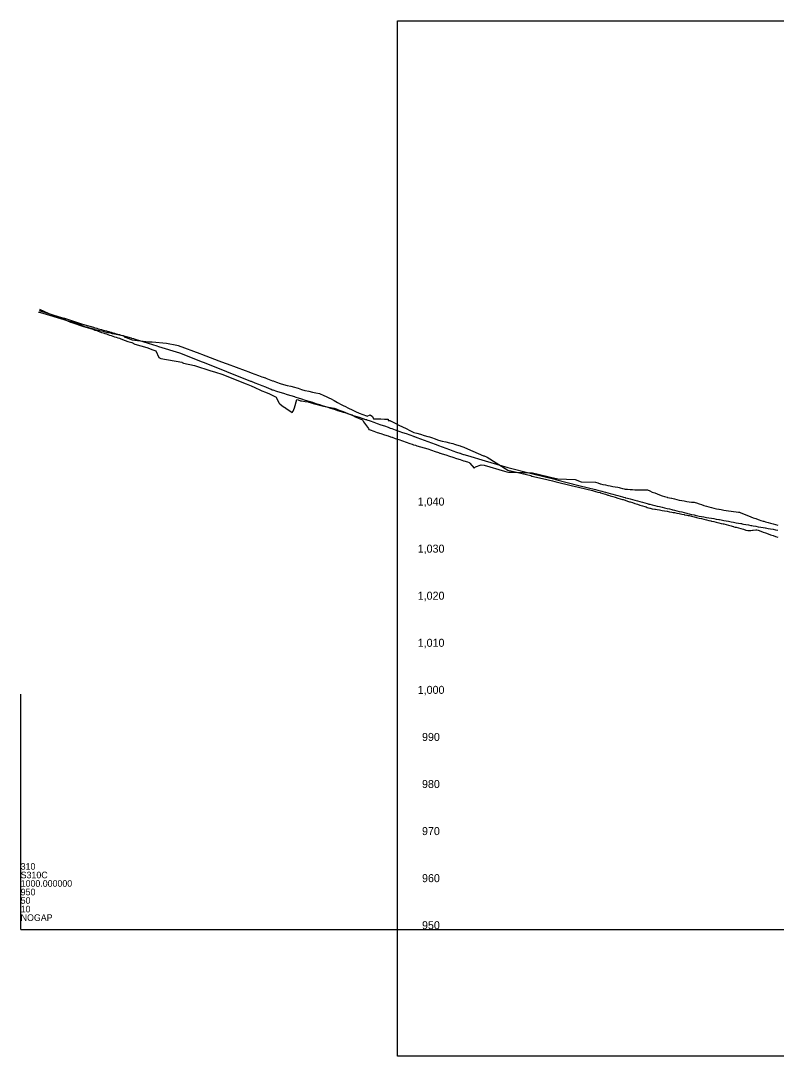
# Model space of a CAD drawing. Extents: x 1590191 to 1593577, y 1108634 to 1115609.
# Drawn here: x 1590279 to 1591081, y 1114509 to 1115609 of the extents above; entities that cross this region are included whole.
import ezdxf

# ---------------------------------------------------------------- set-up
doc = ezdxf.new("R2010")
doc.units = 0
for name, color, linetype in [('BR_EXIST_GROUND_LT', 7, 'Continuous'), ('BR_EXIST_GROUND_RT', 7, 'Continuous'), ('RD_DDB_ElevTX', 7, 'Continuous'), ('RD_DDB_Profile_EX', 7, 'Continuous'), ('RD_GPK_Profile_Cell', 7, 'Continuous'), ('RD_SHT_ShtClip', 7, 'Continuous')]:
    doc.layers.add(name, color=color, linetype=linetype)

msp = doc.modelspace()

# ---------------------------------------------------------------- linework, layer by layer
at = {"layer": 'BR_EXIST_GROUND_LT'}
msp.add_lwpolyline([(1590297.9, 1115299.3), (1590298.7, 1115299.2), (1590302.4, 1115298), (1590324.9, 1115291.5), (1590331.7, 1115289.4), (1590332.7, 1115289.1), (1590334.3, 1115288.6), (1590337, 1115287.9), (1590339.4, 1115287.2), (1590343.4, 1115285.5), (1590347.6, 1115283.6), (1590348.5, 1115283.4), (1590356.2, 1115281.3), (1590357.9, 1115280.8), (1590359.7, 1115280.4), (1590361.2, 1115280), (1590363.1, 1115279.6), (1590364.8, 1115279.2), (1590366.5, 1115278.8), (1590368.3, 1115278.4), (1590370, 1115278), (1590371.7, 1115277.6), (1590372.6, 1115277.4), (1590373.4, 1115277.4), (1590374.4, 1115277.3), (1590375.2, 1115277), (1590376.2, 1115276.6), (1590376.9, 1115276.5), (1590378.6, 1115276.1), (1590380.3, 1115275.7), (1590382, 1115275.4), (1590383.8, 1115275), (1590385.5, 1115274.6), (1590387.2, 1115274.3), (1590387.7, 1115274.2), (1590389.6, 1115272.6), (1590391, 1115272.1), (1590397.5, 1115269.8), (1590414.8, 1115267.6), (1590418.5, 1115267.8), (1590434, 1115266.3), (1590444.9, 1115264), (1590446.3, 1115263.8), (1590469.4, 1115255.1), (1590471.1, 1115254.5), (1590489.5, 1115247.5), (1590496.1, 1115244.8), (1590498.4, 1115244.2), (1590517.4, 1115237.3), (1590521.3, 1115235.6), (1590523.7, 1115234.7), (1590527.5, 1115233.3), (1590531.4, 1115232), (1590535.2, 1115230.6), (1590539, 1115229.3), (1590539.4, 1115229.1), (1590542.8, 1115227.7), (1590546.4, 1115226.3), (1590547, 1115226.1), (1590550.5, 1115224.8), (1590554.6, 1115223.3), (1590558.2, 1115222.3), (1590562, 1115221.3), (1590565.8, 1115220.4), (1590569.6, 1115219.4), (1590572.2, 1115218.8), (1590573.5, 1115218.4), (1590577.3, 1115217.1), (1590580.7, 1115216), (1590581.1, 1115215.9), (1590585, 1115215.1), (1590588.8, 1115214.2), (1590592.6, 1115213.4), (1590596.4, 1115212.7), (1590597.1, 1115212.5), (1590600.3, 1115211), (1590604.1, 1115209.2), (1590606.8, 1115207.9), (1590607.9, 1115207.3), (1590611.8, 1115205.3), (1590615.6, 1115203.2), (1590619.4, 1115201.2), (1590622.3, 1115199.7), (1590623.2, 1115199.2), (1590627.1, 1115197.3), (1590630.9, 1115195.4), (1590633, 1115194.3), (1590634.7, 1115193.6), (1590638.6, 1115192), (1590642.4, 1115190.5), (1590646.2, 1115188.9), (1590647, 1115188.6), (1590650.1, 1115190.2), (1590652.6, 1115188.2), (1590653.8, 1115185.9), (1590655.2, 1115185.9), (1590657.7, 1115185.8), (1590661.5, 1115185.7), (1590665.4, 1115185.6), (1590669.3, 1115185.4), (1590669.3, 1115183.9), (1590671.3, 1115183.9), (1590671.4, 1115183.8), (1590671.8, 1115183.7), (1590673, 1115183.1), (1590676.8, 1115181.1), (1590680.7, 1115179.2), (1590684.5, 1115177.3), (1590688.3, 1115175.4), (1590692.2, 1115173.6), (1590696.6, 1115171.5), (1590699.8, 1115170.5), (1590703.6, 1115169.4), (1590707.5, 1115168.3), (1590711.3, 1115167.2), (1590713.1, 1115166.7), (1590715.1, 1115165.9), (1590719, 1115164.5), (1590721.8, 1115163.5), (1590722.8, 1115163.2), (1590726.6, 1115162.2), (1590730.4, 1115161.3), (1590734.3, 1115160.4), (1590738.1, 1115159.5), (1590739.8, 1115159.1), (1590741.9, 1115158.4), (1590745.8, 1115157.2), (1590746.6, 1115156.9), (1590749.6, 1115155.6), (1590753.4, 1115154), (1590770.4, 1115146.7), (1590771.3, 1115146.6), (1590774.3, 1115145.1), (1590796.5, 1115131.2), (1590820.8, 1115125.5), (1590821.8, 1115125.1), (1590833.3, 1115122.5), (1590843.9, 1115119.9), (1590846.3, 1115119.3), (1590865, 1115114.8), (1590871.5, 1115113.1), (1590886.1, 1115109.6), (1590889.4, 1115108.7), (1590892, 1115108), (1590894.3, 1115107.5), (1590894.6, 1115107.4), (1590897.3, 1115106.5), (1590899.9, 1115105.7), (1590902.5, 1115104.9), (1590903.4, 1115104.6), (1590905.1, 1115104.1), (1590907.7, 1115103.3), (1590910.4, 1115102.5), (1590913, 1115101.7), (1590915.6, 1115100.9), (1590918.2, 1115100.2), (1590918.8, 1115100), (1590920.8, 1115099.3), (1590923.5, 1115098.5), (1590925.4, 1115097.8), (1590926.1, 1115097.6), (1590928.7, 1115096.8), (1590931.3, 1115096), (1590933.9, 1115095.1), (1590936.5, 1115094.3), (1590939.2, 1115093.5), (1590941.8, 1115092.6), (1590943.3, 1115092.2), (1590944.4, 1115091.8), (1590947, 1115090.9), (1590947.4, 1115090.8), (1590949.6, 1115090.4), (1590952.3, 1115090), (1590953.2, 1115089.8), (1590954.9, 1115089.5), (1590957.5, 1115089.1), (1590960.1, 1115088.6), (1590962.7, 1115088.1), (1590965.4, 1115087.6), (1590968, 1115087.1), (1590970.6, 1115086.7), (1590972, 1115086.4), (1590973.2, 1115086.2), (1590975.8, 1115085.7), (1590978.4, 1115085.2), (1590981.1, 1115084.6), (1590983.7, 1115084.1), (1590984.1, 1115084), (1590986.3, 1115083.6), (1590987.7, 1115083.3), (1590988.9, 1115083), (1590991.5, 1115082.4), (1590994.2, 1115081.7), (1590996.8, 1115081.1), (1590999.4, 1115080.5), (1591002, 1115079.9), (1591004.6, 1115079.2), (1591007.3, 1115078.6), (1591009.9, 1115078), (1591011.9, 1115077.5), (1591012.5, 1115077.3), (1591015.1, 1115076.7), (1591017.7, 1115076.1), (1591020.3, 1115075.4), (1591023, 1115074.8), (1591025, 1115074.3), (1591025.6, 1115074.2), (1591028.2, 1115073.5), (1591030.8, 1115072.8), (1591033.4, 1115072.1), (1591034.5, 1115071.8), (1591036.1, 1115071.4), (1591036.5, 1115071.3), (1591037.7, 1115070.9), (1591038.7, 1115070.6), (1591041.3, 1115069.9), (1591043.9, 1115069.2), (1591046.5, 1115068.5), (1591049.2, 1115067.7), (1591051.2, 1115067.1), (1591051.8, 1115067.2), (1591054.4, 1115067.4), (1591056.3, 1115067.6), (1591057, 1115067.6), (1591059.6, 1115067.9), (1591060.9, 1115068), (1591062.2, 1115067.5), (1591064.9, 1115066.6), (1591067.5, 1115065.6), (1591070.1, 1115064.7), (1591072.7, 1115063.7), (1591075.3, 1115062.8), (1591078, 1115061.9), (1591078.3, 1115061.8), (1591080.6, 1115061), (1591083.2, 1115060)], dxfattribs=at)
at = {"layer": 'BR_EXIST_GROUND_RT'}
msp.add_lwpolyline([(1590299.1, 1115302.3), (1590308.8, 1115297.9), (1590316.6, 1115294.5), (1590323.4, 1115292.3), (1590331.8, 1115288.6), (1590334.3, 1115287.8), (1590345.8, 1115284), (1590354.4, 1115281.3), (1590356.2, 1115280.7), (1590357.9, 1115280.1), (1590359.7, 1115279.5), (1590361.4, 1115278.9), (1590363.1, 1115278.3), (1590364.8, 1115277.7), (1590366.5, 1115277.2), (1590368.3, 1115276.6), (1590368.8, 1115276.4), (1590370, 1115276), (1590371.7, 1115275.4), (1590373.4, 1115274.8), (1590375.2, 1115274.3), (1590376.9, 1115273.7), (1590378.6, 1115273.1), (1590380.3, 1115272.5), (1590382, 1115272), (1590383.8, 1115271.4), (1590385.5, 1115270.8), (1590386.4, 1115270.6), (1590387.2, 1115270.2), (1590392.7, 1115268.1), (1590396.9, 1115266.8), (1590400.3, 1115265.3), (1590413.1, 1115261.7), (1590419.5, 1115259.1), (1590422.6, 1115257.9), (1590425.6, 1115250.9), (1590427.8, 1115249.9), (1590450.1, 1115245.9), (1590450.6, 1115245.7), (1590451.8, 1115245.1), (1590463.6, 1115242.4), (1590480.8, 1115236.9), (1590484.7, 1115235.8), (1590493.7, 1115232.9), (1590497.8, 1115231.1), (1590518.5, 1115223.1), (1590523.7, 1115220.8), (1590527.5, 1115219), (1590529.9, 1115217.9), (1590531.4, 1115217.3), (1590535.2, 1115215.7), (1590539, 1115214.1), (1590543.1, 1115212.4), (1590544, 1115212), (1590546.7, 1115210.7), (1590550.2, 1115209), (1590550.5, 1115208.2), (1590553, 1115202.8), (1590554.3, 1115201.8), (1590558.2, 1115198.7), (1590559, 1115198.1), (1590562, 1115196.1), (1590565.8, 1115193.6), (1590567.3, 1115192.6), (1590568.5, 1115194.1), (1590569.6, 1115197.7), (1590572.4, 1115206.4), (1590573.5, 1115206), (1590576.1, 1115205.1), (1590577.3, 1115204.9), (1590581.1, 1115204.4), (1590584.3, 1115204), (1590585, 1115203.7), (1590588.8, 1115202.6), (1590589.7, 1115202.3), (1590592.6, 1115201.4), (1590595.2, 1115200.6), (1590596.4, 1115200.4), (1590600.5, 1115199.4), (1590604.1, 1115198.7), (1590607.9, 1115197.8), (1590611.8, 1115197), (1590614.1, 1115196.5), (1590615.6, 1115195.9), (1590619.4, 1115194.4), (1590620.3, 1115194), (1590623.2, 1115192.8), (1590627.1, 1115191.3), (1590630.9, 1115189.7), (1590632.8, 1115188.9), (1590634.7, 1115188), (1590638.6, 1115186.2), (1590640.3, 1115185.4), (1590642.1, 1115184.7), (1590643.1, 1115182.7), (1590646.2, 1115178.3), (1590648.2, 1115175.5), (1590648.7, 1115174.5), (1590650, 1115174.1), (1590653.9, 1115172.8), (1590657.7, 1115171.5), (1590661.5, 1115170.3), (1590665.4, 1115169), (1590669.2, 1115167.7), (1590671.9, 1115166.7), (1590673, 1115166.4), (1590673.4, 1115166.3), (1590676.8, 1115165.1), (1590680.7, 1115163.8), (1590684.5, 1115162.4), (1590688.3, 1115161.1), (1590692.2, 1115159.7), (1590694.6, 1115158.9), (1590696, 1115158.4), (1590698.2, 1115157.7), (1590699.8, 1115157.1), (1590703.6, 1115156), (1590707.5, 1115154.9), (1590711.4, 1115153.8), (1590715.1, 1115152.5), (1590719, 1115151.2), (1590722.8, 1115150), (1590724.1, 1115149.5), (1590724.4, 1115149.4), (1590726.6, 1115148.8), (1590730.4, 1115147.5), (1590734.3, 1115146.2), (1590738.1, 1115145), (1590741.9, 1115143.7), (1590745.8, 1115142.5), (1590749.2, 1115141.3), (1590749.6, 1115141.2), (1590753.4, 1115140), (1590755.4, 1115139.3), (1590756, 1115138.7), (1590760.6, 1115133.5), (1590762.1, 1115134.7), (1590768.1, 1115137.1), (1590771.1, 1115136.5), (1590792.8, 1115130.3), (1590795.2, 1115129.7), (1590797.2, 1115129.1), (1590802.2, 1115129.1), (1590822.6, 1115128.6), (1590847.6, 1115122.6), (1590848.1, 1115122.5), (1590849.3, 1115122.2), (1590867.8, 1115121.5), (1590874.2, 1115119), (1590889.4, 1115118.6), (1590892, 1115117.7), (1590894.3, 1115116.9), (1590894.6, 1115116.8), (1590897.3, 1115116.2), (1590899.9, 1115115.6), (1590902.5, 1115115), (1590905.1, 1115114.5), (1590907.7, 1115114), (1590910.4, 1115113.5), (1590913, 1115113.1), (1590914.5, 1115112.9), (1590915.6, 1115112.6), (1590918.2, 1115111.8), (1590919.8, 1115111.4), (1590920.8, 1115111.3), (1590923.5, 1115111), (1590926.1, 1115110.9), (1590928.7, 1115110.7), (1590931.3, 1115110.6), (1590933.9, 1115110.6), (1590936.5, 1115110.5), (1590939.2, 1115110.6), (1590941.8, 1115110.6), (1590944.5, 1115110.3), (1590947, 1115109.2), (1590949.6, 1115108.1), (1590952.3, 1115107.1), (1590954.9, 1115106.1), (1590957.5, 1115105.1), (1590960.1, 1115104.2), (1590962.7, 1115103.4), (1590965.4, 1115102.6), (1590965.8, 1115102.4), (1590968, 1115102), (1590970.1, 1115101.6), (1590970.6, 1115101.5), (1590973.2, 1115100.8), (1590975.8, 1115100.2), (1590978.4, 1115099.6), (1590981.1, 1115099.1), (1590983.7, 1115098.6), (1590986.3, 1115098.1), (1590988.9, 1115097.7), (1590991.5, 1115097.4), (1590992.3, 1115097.3), (1590994.2, 1115097.2), (1590995.3, 1115097.1), (1590996.8, 1115096.6), (1590999.4, 1115095.7), (1591002, 1115094.8), (1591004.6, 1115093.9), (1591007.3, 1115093.2), (1591009.9, 1115092.4), (1591012.5, 1115091.7), (1591015.1, 1115091), (1591017.8, 1115090.4), (1591020.3, 1115090), (1591020.8, 1115089.9), (1591023, 1115089.5), (1591025.6, 1115089), (1591028.2, 1115088.5), (1591030.8, 1115088.1), (1591033.4, 1115087.7), (1591036.1, 1115087.3), (1591038.7, 1115087), (1591041.3, 1115086.7), (1591042.5, 1115086.7), (1591043.9, 1115086.1), (1591046.5, 1115084.9), (1591049.2, 1115083.8), (1591051.8, 1115082.8), (1591054.4, 1115081.7), (1591057, 1115080.7), (1591059.6, 1115079.8), (1591062.2, 1115078.9), (1591063.3, 1115078.5), (1591064.9, 1115078), (1591067.5, 1115077.2), (1591068.1, 1115077), (1591070.1, 1115076.4), (1591072.7, 1115075.6), (1591075.3, 1115074.9), (1591078, 1115074.2), (1591080.6, 1115073.5), (1591083.2, 1115072.9)], dxfattribs=at)
at = {"layer": 'RD_DDB_Profile_EX'}
msp.add_lwpolyline([(1590298.6, 1115300.9), (1590298.6, 1115300.9), (1590319.7, 1115294.3), (1590323.9, 1115293.1), (1590325.4, 1115292.6), (1590345.7, 1115286.2), (1590346.2, 1115286), (1590347, 1115285.7), (1590356.2, 1115283.1), (1590357.9, 1115282.6), (1590359.7, 1115282.1), (1590361.4, 1115281.6), (1590363.1, 1115281.2), (1590364.8, 1115280.7), (1590366.5, 1115280.2), (1590368.3, 1115279.7), (1590370, 1115279.2), (1590370.9, 1115279), (1590371.8, 1115278.7), (1590372.5, 1115278.5), (1590373.4, 1115278.3), (1590375.2, 1115277.8), (1590376.9, 1115277.3), (1590378.6, 1115276.8), (1590380.3, 1115276.3), (1590382, 1115275.8), (1590383.8, 1115275.3), (1590385.5, 1115274.8), (1590387.2, 1115274.3), (1590396.3, 1115271.8), (1590396.8, 1115271.5), (1590398.7, 1115271), (1590400.5, 1115270.4), (1590423.6, 1115263.4), (1590425.3, 1115262.8), (1590447.8, 1115256), (1590471.6, 1115246.4), (1590472.7, 1115246), (1590473.8, 1115245.6), (1590497.6, 1115236.1), (1590498.3, 1115235.8), (1590499.3, 1115235.4), (1590523.2, 1115225.9), (1590523.7, 1115225.7), (1590527.5, 1115224.2), (1590531.4, 1115222.7), (1590535.2, 1115221.2), (1590539, 1115219.7), (1590542.8, 1115218.1), (1590544.9, 1115217.3), (1590546.2, 1115216.8), (1590546.7, 1115216.6), (1590550.5, 1115215.4), (1590554.3, 1115214.3), (1590558.2, 1115213.1), (1590562, 1115211.8), (1590565.8, 1115210.6), (1590569.6, 1115209.4), (1590570, 1115209.3), (1590571.1, 1115209), (1590573.5, 1115208.2), (1590577.3, 1115207), (1590581.1, 1115205.8), (1590585, 1115204.6), (1590588.8, 1115203.4), (1590592.6, 1115202.1), (1590595.8, 1115201.1), (1590596.4, 1115200.9), (1590600.3, 1115199.7), (1590604.1, 1115198.5), (1590607.9, 1115197.3), (1590611.8, 1115196.1), (1590615.6, 1115194.8), (1590619.4, 1115193.6), (1590620.8, 1115193.2), (1590621.1, 1115193.1), (1590623.2, 1115192.4), (1590627.1, 1115191.2), (1590630.9, 1115190), (1590632.2, 1115189.5), (1590634.7, 1115188.7), (1590638.6, 1115187.5), (1590642.4, 1115186.3), (1590645.3, 1115185.3), (1590646.2, 1115185), (1590646.7, 1115184.9), (1590650, 1115183.7), (1590653.9, 1115182.3), (1590657.7, 1115181), (1590661.5, 1115179.6), (1590665.4, 1115178.3), (1590669.2, 1115176.9), (1590671.5, 1115176.1), (1590671.9, 1115176), (1590673, 1115175.6), (1590676.8, 1115174.2), (1590680.7, 1115172.8), (1590684.5, 1115171.5), (1590688.3, 1115170.1), (1590692.2, 1115168.7), (1590696, 1115167.4), (1590696.5, 1115167.2), (1590697.2, 1115166.9), (1590699.8, 1115166), (1590703.6, 1115164.6), (1590707.5, 1115163.2), (1590711.3, 1115161.8), (1590715.1, 1115160.4), (1590719, 1115159), (1590722.1, 1115157.9), (1590722.8, 1115157.6), (1590726.6, 1115156.2), (1590730.4, 1115154.8), (1590734.3, 1115153.4), (1590738.1, 1115152), (1590741.9, 1115150.6), (1590745.4, 1115149.4), (1590745.8, 1115149.2), (1590747.1, 1115148.8), (1590749.1, 1115148.1), (1590749.6, 1115148), (1590753.4, 1115146.9), (1590772.2, 1115141.2), (1590796.5, 1115134), (1590821.5, 1115127.8), (1590846.4, 1115121.6), (1590846.9, 1115121.5), (1590871.9, 1115115.1), (1590889.4, 1115110.7), (1590892, 1115110), (1590894.7, 1115109.3), (1590896.3, 1115109), (1590897.3, 1115108.7), (1590899.9, 1115108), (1590902.5, 1115107.3), (1590905.1, 1115106.5), (1590907.7, 1115105.8), (1590910.4, 1115105.1), (1590913, 1115104.4), (1590915.6, 1115103.7), (1590918.2, 1115102.9), (1590919.1, 1115102.7), (1590920.8, 1115102.2), (1590921.3, 1115102.1), (1590923.5, 1115101.5), (1590926.1, 1115100.8), (1590928.7, 1115100.1), (1590931.3, 1115099.4), (1590933.9, 1115098.6), (1590936.5, 1115097.9), (1590939.2, 1115097.2), (1590941.8, 1115096.5), (1590944.4, 1115095.8), (1590945.2, 1115095.6), (1590946.2, 1115095.3), (1590947.2, 1115095.1), (1590949.6, 1115094.5), (1590952.3, 1115093.8), (1590954.9, 1115093.2), (1590957.5, 1115092.6), (1590960.1, 1115091.9), (1590962.7, 1115091.3), (1590965.4, 1115090.7), (1590968, 1115090.1), (1590970.6, 1115089.4), (1590971.2, 1115089.3), (1590972.1, 1115089.1), (1590973.2, 1115088.8), (1590975.8, 1115088.2), (1590978.4, 1115087.5), (1590981.1, 1115086.9), (1590983.7, 1115086.3), (1590986.3, 1115085.6), (1590987.3, 1115085.4), (1590988.9, 1115085), (1590991.5, 1115084.3), (1590994.2, 1115083.7), (1590995.3, 1115083.4), (1590996, 1115083.2), (1590996.8, 1115083.1), (1590999.4, 1115082.6), (1591002, 1115082.2), (1591004.6, 1115081.7), (1591007.3, 1115081.2), (1591009.9, 1115080.8), (1591012.5, 1115080.3), (1591015.2, 1115079.8), (1591017.7, 1115079.4), (1591020.3, 1115078.9), (1591021, 1115078.8), (1591023, 1115078.4), (1591025.8, 1115077.9), (1591028.2, 1115077.5), (1591030.8, 1115077), (1591033.4, 1115076.5), (1591036.1, 1115076), (1591038.7, 1115075.5), (1591041.3, 1115075.1), (1591043.9, 1115074.6), (1591044.6, 1115074.5), (1591045.3, 1115074.3), (1591046.5, 1115074.1), (1591049.2, 1115073.7), (1591051.8, 1115073.2), (1591054.4, 1115072.7), (1591055.3, 1115072.6), (1591057, 1115072.3), (1591059.6, 1115071.8), (1591062.2, 1115071.3), (1591064.9, 1115070.8), (1591067.5, 1115070.4), (1591069.6, 1115070), (1591070.1, 1115069.9), (1591072.7, 1115069.4), (1591075.3, 1115068.9), (1591078, 1115068.5), (1591080.6, 1115068), (1591083.2, 1115067.5)], dxfattribs=at)
at = {"layer": 'RD_GPK_Profile_Cell'}
for q in [(1590279, 1114893.5), (1593576.8, 1114643.5), (1590279, 1114643.5)]:
    msp.add_line((1590279, 1114643.5), q, dxfattribs=at)
at = {"layer": 'RD_SHT_ShtClip'}
msp.add_lwpolyline([(1590679, 1115608.7), (1592479, 1115608.7), (1592479, 1114508.7), (1590679, 1114508.7)], close=True, dxfattribs=at)

# ---------------------------------------------------------------- texts
at = {"layer": 'RD_DDB_ElevTX'}
for s, p in [('1,040', (1590700.6, 1115093.7)), ('1,030', (1590700.6, 1115043.7)), ('1,020', (1590700.6, 1114993.7)), ('1,010', (1590700.6, 1114943.7)), ('1,000', (1590700.6, 1114893.7)), ('990', (1590705.2, 1114843.7)), ('980', (1590705.2, 1114793.7)), ('970', (1590705.2, 1114743.7)), ('960', (1590705.2, 1114693.7)), ('950', (1590705.2, 1114643.7))]:
    msp.add_text(s, height=8.5, dxfattribs=at).set_placement(p)
at = {"layer": 'RD_GPK_Profile_Cell'}
for s, p in [('310', (1590279, 1114706.9)), ('S310C', (1590279, 1114697.8)), ('950', (1590279, 1114679.7)), ('1000.000000', (1590279, 1114688.8)), ('50', (1590279, 1114670.7)), ('10', (1590279, 1114661.6)), ('NOGAP', (1590279, 1114652.5))]:
    msp.add_text(s, height=7, dxfattribs=at).set_placement(p)

doc.saveas('drawing.dxf')
